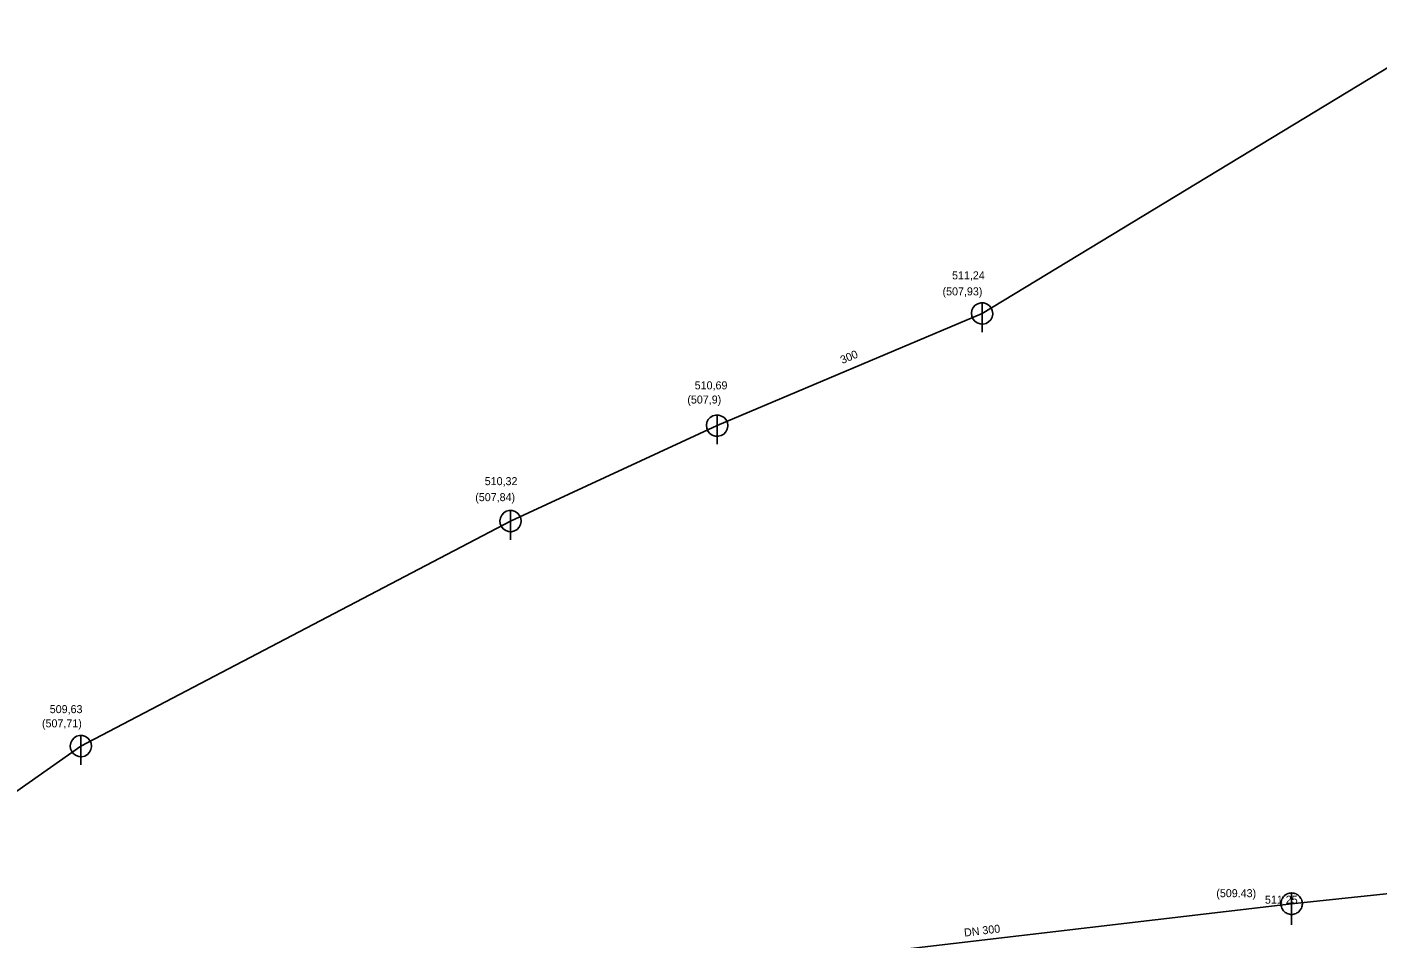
# Model space of a CAD drawing. Extents: x -476058 to -471893, y -1155786 to -1152000.
# Drawn here: x -475058.6 to -474932.1, y -1154167.1 to -1154081.7 of the extents above; entities that cross this region are included whole.
import ezdxf

# ---------------------------------------------------------------- set-up
doc = ezdxf.new("R2010")
doc.units = 0
for name, color, linetype in [('Vrstva 1', 7, 'Continuous'), ('Vrstva 10', 7, 'Continuous'), ('Vrstva 16', 7, 'Continuous'), ('Vrstva 18', 7, 'Continuous'), ('Vrstva 3', 7, 'Continuous'), ('Vrstva 35', 7, 'Continuous'), ('Vrstva 4', 7, 'Continuous'), ('Vrstva 45', 7, 'Continuous')]:
    doc.layers.add(name, color=color, linetype=linetype)

msp = doc.modelspace()

# ---------------------------------------------------------------- linework, layer by layer
at = {"layer": 'Vrstva 1'}
msp.add_line((-474940.09, -1154163.87), (-474940.09, -1154163.87), dxfattribs=at)
at = {"layer": 'Vrstva 10'}
for p, q in [((-474969.11, -1154107.55), (-474969.11, -1154110.3)), ((-474993.94, -1154118.06), (-474993.94, -1154120.81)), ((-475013.3, -1154127), (-475013.3, -1154129.75)), ((-475053.57, -1154148.1), (-475053.57, -1154150.85))]:
    msp.add_line(p, q, dxfattribs=at)
for points in [[(-474968.11, -1154108.55), (-474968.15, -1154108.27), (-474968.26, -1154108.01), (-474968.45, -1154107.8), (-474968.68, -1154107.65), (-474968.95, -1154107.56), (-474969.23, -1154107.56), (-474969.51, -1154107.63), (-474969.74, -1154107.78), (-474969.93, -1154107.99), (-474970.06, -1154108.24), (-474970.11, -1154108.52), (-474970.07, -1154108.8), (-474969.97, -1154109.06), (-474969.79, -1154109.28), (-474969.56, -1154109.44), (-474969.29, -1154109.53), (-474969.01, -1154109.55), (-474968.73, -1154109.48), (-474968.49, -1154109.34), (-474968.29, -1154109.13), (-474968.16, -1154108.88), (-474968.11, -1154108.61), (-474968.11, -1154108.55)], [(-474992.94, -1154119.06), (-474992.98, -1154118.78), (-474993.1, -1154118.52), (-474993.28, -1154118.31), (-474993.52, -1154118.16), (-474993.79, -1154118.07), (-474994.07, -1154118.07), (-474994.34, -1154118.14), (-474994.58, -1154118.29), (-474994.77, -1154118.5), (-474994.89, -1154118.75), (-474994.94, -1154119.03), (-474994.91, -1154119.31), (-474994.8, -1154119.57), (-474994.62, -1154119.79), (-474994.39, -1154119.95), (-474994.12, -1154120.04), (-474993.84, -1154120.06), (-474993.57, -1154119.99), (-474993.32, -1154119.85), (-474993.13, -1154119.64), (-474993, -1154119.39), (-474992.94, -1154119.12), (-474992.94, -1154119.06)], [(-475012.3, -1154128), (-475012.34, -1154127.72), (-475012.46, -1154127.47), (-475012.64, -1154127.25), (-475012.88, -1154127.1), (-475013.15, -1154127.01), (-475013.43, -1154127.01), (-475013.7, -1154127.08), (-475013.94, -1154127.23), (-475014.13, -1154127.44), (-475014.25, -1154127.7), (-475014.3, -1154127.97), (-475014.27, -1154128.26), (-475014.16, -1154128.52), (-475013.98, -1154128.73), (-475013.75, -1154128.9), (-475013.48, -1154128.99), (-475013.2, -1154129), (-475012.93, -1154128.93), (-475012.68, -1154128.79), (-475012.49, -1154128.58), (-475012.36, -1154128.33), (-475012.3, -1154128.06), (-475012.3, -1154128)], [(-475052.57, -1154149.1), (-475052.61, -1154148.82), (-475052.73, -1154148.56), (-475052.91, -1154148.35), (-475053.15, -1154148.2), (-475053.42, -1154148.11), (-475053.7, -1154148.11), (-475053.97, -1154148.18), (-475054.21, -1154148.33), (-475054.4, -1154148.54), (-475054.52, -1154148.79), (-475054.57, -1154149.07), (-475054.54, -1154149.35), (-475054.43, -1154149.61), (-475054.25, -1154149.83), (-475054.02, -1154149.99), (-475053.75, -1154150.08), (-475053.47, -1154150.1), (-475053.2, -1154150.03), (-475052.95, -1154149.89), (-475052.76, -1154149.68), (-475052.63, -1154149.43), (-475052.57, -1154149.16), (-475052.57, -1154149.1)], [(-474939.08, -1154163.87), (-474939.09, -1154163.77), (-474939.1, -1154163.66), (-474939.13, -1154163.56), (-474939.17, -1154163.46), (-474939.22, -1154163.37), (-474939.28, -1154163.28), (-474939.34, -1154163.2), (-474939.42, -1154163.12), (-474939.5, -1154163.05), (-474939.59, -1154163), (-474939.68, -1154162.95), (-474939.78, -1154162.91), (-474939.88, -1154162.88), (-474939.98, -1154162.87), (-474940.09, -1154162.86), (-474940.2, -1154162.87), (-474940.3, -1154162.88), (-474940.4, -1154162.91), (-474940.5, -1154162.95), (-474940.59, -1154163), (-474940.68, -1154163.05), (-474940.77, -1154163.12), (-474940.84, -1154163.2), (-474940.91, -1154163.28), (-474940.96, -1154163.37), (-474941.01, -1154163.46), (-474941.05, -1154163.56), (-474941.08, -1154163.66), (-474941.09, -1154163.77), (-474941.1, -1154163.87), (-474941.09, -1154163.98), (-474941.08, -1154164.08), (-474941.05, -1154164.18), (-474941.01, -1154164.28), (-474940.96, -1154164.37), (-474940.91, -1154164.46), (-474940.84, -1154164.54), (-474940.77, -1154164.62), (-474940.68, -1154164.69), (-474940.59, -1154164.74), (-474940.5, -1154164.79), (-474940.4, -1154164.83), (-474940.3, -1154164.86), (-474940.2, -1154164.87), (-474940.09, -1154164.88), (-474939.98, -1154164.87), (-474939.88, -1154164.86), (-474939.78, -1154164.83), (-474939.68, -1154164.79), (-474939.59, -1154164.74), (-474939.5, -1154164.69), (-474939.42, -1154164.62), (-474939.34, -1154164.54), (-474939.28, -1154164.46), (-474939.22, -1154164.37), (-474939.17, -1154164.28), (-474939.13, -1154164.18), (-474939.1, -1154164.08), (-474939.09, -1154163.98), (-474939.08, -1154163.87)], [(-474940.09, -1154162.86), (-474940.09, -1154165.84)]]:
    msp.add_lwpolyline(points, dxfattribs=at)
at = {"layer": 'Vrstva 35'}
msp.add_lwpolyline([(-474850.38, -1154154.67), (-474890.71, -1154158.68), (-474940.09, -1154163.87), (-474990.69, -1154169.83), (-475017.24, -1154174.14), (-475043.32, -1154186.7), (-475043.59, -1154187.73)], dxfattribs=at)
at = {"layer": 'Vrstva 45'}
for points in [[(-474924.83, -1154081.7), (-474969.11, -1154108.55)], [(-474969.11, -1154108.55), (-474993.94, -1154119.06)], [(-474993.94, -1154119.06), (-475013.3, -1154128)], [(-475013.3, -1154128), (-475053.57, -1154149.1)], [(-475053.57, -1154149.1), (-475066.46, -1154158.12)]]:
    msp.add_lwpolyline(points, dxfattribs=at)

# ---------------------------------------------------------------- texts
at = {"layer": 'Vrstva 16'}
msp.add_text('DN 300', height=0.75, rotation=6.7245, dxfattribs=at).set_placement((-474970.75, -1154166.96))
at = {"layer": 'Vrstva 18'}
msp.add_text('300 ', height=0.75, rotation=22.9386, dxfattribs=at).set_placement((-474982.2, -1154113.29))
at = {"layer": 'Vrstva 3'}
for s, p in [('511,24', (-474971.92, -1154105.35)), ('510,69', (-474996.04, -1154115.66)), ('510,32', (-475015.72, -1154124.64)), ('509,63', (-475056.49, -1154146.01)), ('511 25 ', (-474942.59, -1154163.87))]:
    msp.add_text(s, height=0.75, dxfattribs=at).set_placement(p)
at = {"layer": 'Vrstva 4'}
for s, p in [('(507,93)', (-474972.81, -1154106.85)), ('(507,9)', (-474996.73, -1154116.99)), ('(507,84)', (-475016.61, -1154126.14)), ('(507,71)', (-475057.22, -1154147.34)), ('(509.43) ', (-474947.15, -1154163.26))]:
    msp.add_text(s, height=0.75, dxfattribs=at).set_placement(p)

doc.saveas('drawing.dxf')
